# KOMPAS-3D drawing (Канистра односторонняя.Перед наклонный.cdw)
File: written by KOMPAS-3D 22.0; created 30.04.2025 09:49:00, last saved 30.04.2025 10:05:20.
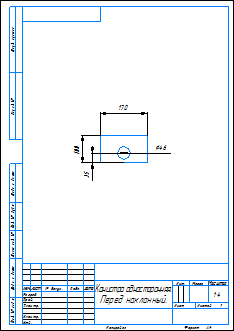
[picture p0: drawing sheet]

Sheet 1: A4, portrait

Document properties: Автор: Admin; Наименование: Канистра односторонняя. Перед наклонный; Полное имя файла: D:\28.11.2016\3D модели\Абилимпикс\2025\Канистра односторонняя\Канистра односторонняя.Перед наклонный.cdw

Title block, sheet 1: Наименование: Канистра односторонняя. / Перед наклонный.; scale: 1:4; Количество листов документа: 1; Форматы листов документа: A4; stored path: D:\28.11.2016\3D модели\Абилимпикс\2025\Канистра односторонняя\Канистра односторонняя.Зад.cdw

Dimensions and other numbers on the sheet: 170; 100; 46; 35; 1:4; 1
